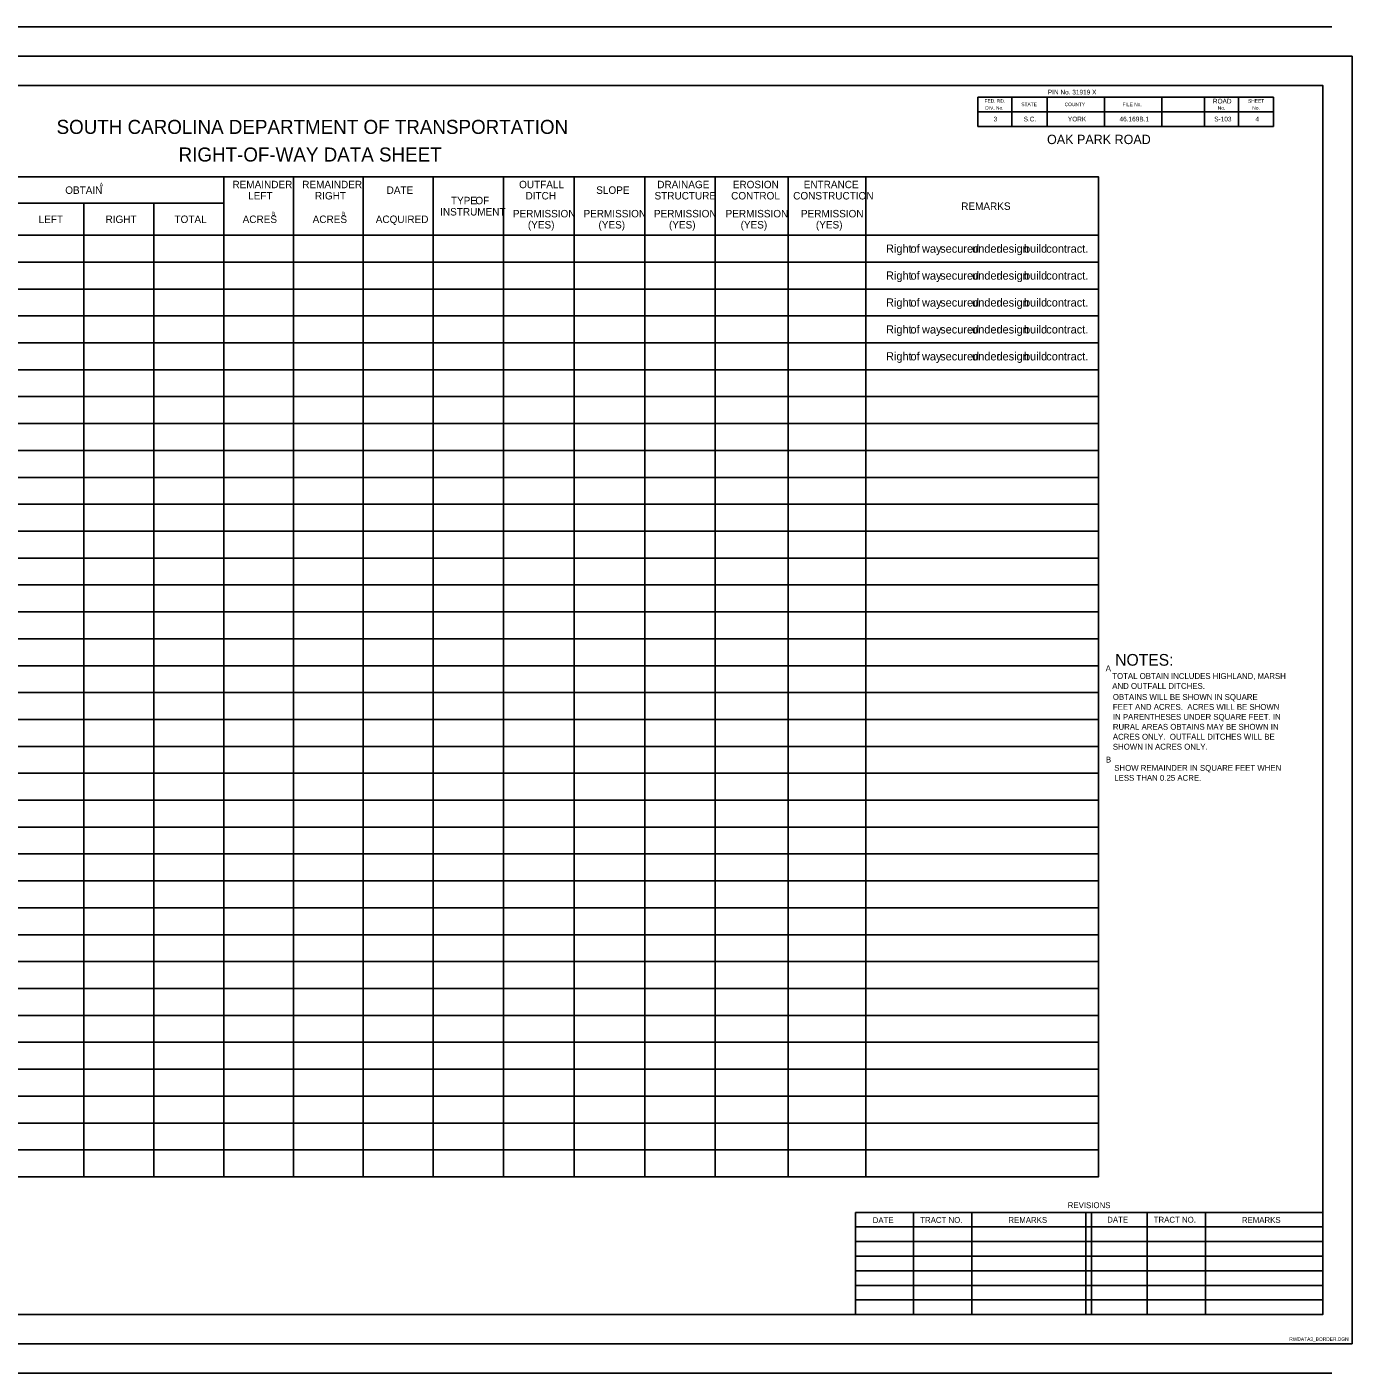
# Model space of a CAD drawing. Extents: x 9981 to 11777, y 9975 to 11125.
# Drawn here: x 10646 to 11777, y 9975 to 11125 of the extents above; entities that cross this region are included whole.
import ezdxf

# ---------------------------------------------------------------- set-up
doc = ezdxf.new("R2010")
doc.units = 0
for name, color, linetype in [('RD_SHT_Bndy', 7, 'Continuous'), ('RD_SHT_IplotShp', 7, 'Continuous'), ('RD_SHT_MjGrid', 7, 'Continuous'), ('RD_SHT_TX', 7, 'Continuous'), ('RD_TX_RW', 7, 'Continuous')]:
    doc.layers.add(name, color=color, linetype=linetype)

msp = doc.modelspace()

# ---------------------------------------------------------------- linework, layer by layer
at = {"layer": 'RD_SHT_Bndy'}
for p, q in [((10000, 11125), (11760, 11125)), ((10000, 11100), (11760, 11100)), ((11457.9, 11065), (11710.4, 11065)), ((11457.9, 11065), (11457.9, 11052.5)), ((11486.9, 11065), (11486.9, 11052.5)), ((11516.9, 11065), (11516.9, 11052.5)), ((11565.9, 11065), (11565.9, 11052.5)), ((11614.9, 11065), (11614.9, 11052.5)), ((11651.4, 11065), (11651.4, 11052.5)), ((11680.4, 11065), (11680.4, 11052.5)), ((11710.4, 11065), (11710.4, 11052.5)), ((11457.9, 11052.5), (11710.4, 11052.5)), ((11457.9, 11052.5), (11457.9, 11040)), ((11486.9, 11052.5), (11486.9, 11049.4)), ((11516.9, 11052.5), (11516.9, 11040)), ((11565.9, 11052.5), (11565.9, 11040)), ((11614.9, 11052.5), (11614.9, 11040)), ((11651.4, 11052.5), (11651.4, 11040)), ((11680.4, 11052.5), (11680.4, 11040)), ((11710.4, 11052.5), (11710.4, 11040)), ((11457.9, 11040), (11710.4, 11040)), ((11486.9, 11049.4), (11486.9, 11040)), ((11353.4, 10112.2), (11752.4, 10112.2)), ((11353.4, 10112.2), (11353.4, 10025)), ((11402.9, 10112.2), (11402.9, 10025)), ((11452.7, 10112.2), (11452.7, 10025)), ((11549.9, 10112.2), (11549.9, 10025)), ((11554.9, 10112.2), (11554.9, 10025)), ((11602.3, 10112.2), (11602.3, 10025)), ((11652.1, 10112.2), (11652.1, 10025)), ((11353.4, 10099.8), (11752.4, 10099.8)), ((11353.4, 10087.3), (11752.4, 10087.3)), ((11353.4, 10074.9), (11752.4, 10074.9)), ((11353.4, 10062.4), (11752.4, 10062.4)), ((11353.4, 10049.9), (11752.4, 10049.9)), ((11353.4, 10037.5), (11752.4, 10037.5)), ((10000, 10000), (11760, 10000)), ((10000, 9975), (11760, 9975))]:
    msp.add_line(p, q, dxfattribs=at)
for points in [[(10077.4, 11075), (11752.4, 11075), (11752.4, 10025), (10077.4, 10025)], [(10218, 10142.7), (11560.9, 10142.7), (11560.9, 10996.8), (10218, 10996.8)]]:
    msp.add_lwpolyline(points, close=True, dxfattribs=at)
at = {"layer": 'RD_SHT_IplotShp'}
msp.add_lwpolyline([(9981.4, 11100), (11777.4, 11100), (11777.4, 10000), (9981.4, 10000)], close=True, dxfattribs=at)
at = {"layer": 'RD_SHT_MjGrid'}
for p, q in [((10218, 10996.8), (11560.9, 10996.8)), ((10813.7, 10142.7), (10813.7, 10996.8)), ((10873.3, 10142.7), (10873.3, 10996.8)), ((10932.9, 10142.7), (10932.9, 10996.8)), ((10992.6, 10142.7), (10992.6, 10996.8)), ((11052.8, 10142.7), (11052.8, 10996.8)), ((11113.1, 10142.7), (11113.1, 10996.8)), ((11173.3, 10142.7), (11173.3, 10996.8)), ((11233.6, 10142.7), (11233.6, 10996.8)), ((11295.7, 10142.7), (11295.7, 10996.8)), ((11362.1, 10142.7), (11362.1, 10996.8)), ((11560.9, 10142.7), (11560.9, 10996.8)), ((10575.2, 10974.4), (10813.7, 10974.4)), ((10694.4, 10142.7), (10694.4, 10974.4)), ((10754, 10142.7), (10754, 10974.4)), ((10218, 10947.1), (11560.9, 10947.1)), ((10992.6, 10947.1), (11362.1, 10947.1)), ((11362.1, 10947.1), (11560.9, 10947.1)), ((10218, 10924.1), (11560.9, 10924.1)), ((10218, 10901.1), (11560.9, 10901.1)), ((10218, 10878.1), (11560.9, 10878.1)), ((10218, 10855.1), (11560.9, 10855.1)), ((10218, 10832.1), (11560.9, 10832.1)), ((10218, 10809.2), (11560.9, 10809.2)), ((10218, 10786.2), (11560.9, 10786.2)), ((10218, 10763.2), (11560.9, 10763.2)), ((10218, 10740.2), (11560.9, 10740.2)), ((10218, 10717.2), (11560.9, 10717.2)), ((10218, 10694.3), (11560.9, 10694.3)), ((10218, 10671.3), (11560.9, 10671.3)), ((10218, 10648.3), (11560.9, 10648.3)), ((10218, 10625.3), (11560.9, 10625.3)), ((10218, 10602.3), (11560.9, 10602.3)), ((10218, 10579.3), (11560.9, 10579.3)), ((10218, 10556.4), (11560.9, 10556.4)), ((10218, 10533.4), (11560.9, 10533.4)), ((10218, 10510.4), (11560.9, 10510.4)), ((10218, 10487.4), (11560.9, 10487.4)), ((10218, 10464.4), (11560.9, 10464.4)), ((10218, 10441.4), (11560.9, 10441.4)), ((10218, 10418.5), (11560.9, 10418.5)), ((10218, 10395.5), (11560.9, 10395.5)), ((10218, 10372.5), (11560.9, 10372.5)), ((10218, 10349.5), (11560.9, 10349.5)), ((10218, 10326.5), (11560.9, 10326.5)), ((10218, 10303.6), (11560.9, 10303.6)), ((10218, 10280.6), (11560.9, 10280.6)), ((10218, 10257.6), (11560.9, 10257.6)), ((10218, 10234.6), (11560.9, 10234.6)), ((10218, 10211.6), (11560.9, 10211.6)), ((10218, 10188.6), (11560.9, 10188.6)), ((10218, 10165.7), (11560.9, 10165.7)), ((10218, 10142.7), (11560.9, 10142.7))]:
    msp.add_line(p, q, dxfattribs=at)

# ---------------------------------------------------------------- texts
at = {"layer": 'RD_SHT_TX'}
for s, height, p in [('FED. RD.', 3, (11463.5, 11060.3)), ('PIN No. 31919 X   ', 4, (11517.6, 11067.3)), ('      ROAD      ', 4, (11649.3, 11059.6)), ('SHEET', 3, (11688.5, 11060.3)), ('DIV. No.', 3, (11464.1, 11054.3)), ('STATE', 3, (11494.9, 11057.3)), ('COUNTY', 3, (11531.9, 11057.3)), ('FILE No.', 3, (11581.4, 11057.3)), ('No.', 3, (11662.7, 11054.3)), ('No.', 3, (11692.2, 11054.3)), ('SOUTH CAROLINA DEPARTMENT OF TRANSPORTATION', 12, (10671, 11033.6)), ('3', 4, (11471.2, 11044.3)), ('S.C.', 4, (11496.9, 11044.3)), ('      YORK      ', 4, (11525.5, 11044.3)), ('   46.169B.1    ', 4, (11574.2, 11044.3)), ('     S-103      ', 4, (11652, 11044.3)), ('       4        ', 4, (11684.1, 11044.3)), ('OAK PARK ROAD                  ', 8, (11516.9, 11024.9)), ('RIGHT-OF-WAY DATA SHEET', 12, (10775.2, 11010)), ('NOTES:', 10, (11575.1, 10579.3)), ('A', 5, (11567, 10574.6)), ('TOTAL OBTAIN INCLUDES HIGHLAND, MARSH', 5, (11572.6, 10568)), ('AND OUTFALL DITCHES. ', 5, (11572.6, 10559.5)), ('OBTAINS WILL BE SHOWN IN SQUARE', 5, (11573.1, 10550.1)), ('FEET AND ACRES.  ACRES WILL BE SHOWN ', 5, (11573.1, 10541.6)), ('IN PARENTHESES UNDER SQUARE FEET. IN ', 5, (11573.1, 10533.1)), ('RURAL AREAS OBTAINS MAY BE SHOWN IN', 5, (11573.1, 10524.6)), ('ACRES ONLY.  OUTFALL DITCHES WILL BE', 5, (11573.1, 10516.1)), ('SHOWN IN ACRES ONLY.', 5, (11573.1, 10507.6)), ('B', 5, (11567.2, 10496.6)), ('SHOW REMAINDER IN SQUARE FEET WHEN ', 5, (11574.3, 10489.5)), ('LESS THAN 0.25 ACRE.', 5, (11574.3, 10481)), ('REVISIONS', 5, (11534.6, 10115.9)), ('DATE', 5, (11568.3, 10103.5)), ('TRACT NO.', 5, (11608, 10103.5)), ('DATE', 5, (11368, 10103.1)), ('TRACT NO.', 5, (11408.6, 10103.3)), ('REMARKS', 5, (11483.9, 10103.3)), ('REMARKS', 5, (11683.3, 10103.3)), ('RWDATA3_BORDER.DGN', 3, (11723.8, 10002.5))]:
    msp.add_text(s, height=height, dxfattribs=at).set_placement(p)
at = {"layer": 'RD_TX_RW'}
for s, height, p in [('OBTAIN', 6.37, (10678.4, 10982.4)), ('A', 3.19, (10707.8, 10988.8)), ('REMAINDER', 6.37, (10821.2, 10987.2)), ('LEFT', 6.37, (10834.6, 10977.6)), ('REMAINDER', 6.37, (10880.8, 10987.2)), ('RIGHT', 6.37, (10891.7, 10977.6)), ('DATE', 6.37, (10952.9, 10982.4)), ('OUTFALL', 6.37, (11066, 10987.2)), ('DITCH', 6.37, (11071.5, 10977.6)), ('SLOPE', 6.37, (11131.9, 10982.4)), ('STRUCTURE', 6.37, (11181.7, 10977.6)), ('DRAINAGE', 6.37, (11184, 10987.2)), ('CONTROL', 6.37, (11247.1, 10977.6)), ('EROSION', 6.37, (11248.5, 10987.2)), ('CONSTRUCTION', 6.371, (11300.1, 10977.6)), ('ENTRANCE', 6.37, (11309.1, 10987.2)), ('TYPE', 6.37, (11007.8, 10973.5)), (' OF', 6.37, (11026.3, 10973.5)), ('REMARKS', 6.37, (11443.6, 10968.7)), ('LEFT', 6.37, (10655.7, 10957.5)), ('RIGHT', 6.37, (10712.8, 10957.5)), ('TOTAL', 6.37, (10771.7, 10957.5)), ('ACRES', 6.37, (10829.9, 10957.5)), ('B', 3.19, (10854.8, 10963.9)), ('ACRES', 6.37, (10889.7, 10957.5)), (' B', 3.19, (10913.4, 10963.9)), ('ACQUIRED', 6.37, (10943.6, 10957.5)), ('INSTRUMENT', 6.37, (10998.6, 10963.9)), ('PERMISSION', 6.37, (11060.7, 10962.3)), ('PERMISSION', 6.37, (11121, 10962.3)), ('PERMISSION', 6.37, (11181.2, 10962.3)), ('PERMISSION', 6.37, (11242.4, 10962.3)), ('PERMISSION', 6.37, (11306.7, 10962.3)), ('(YES)', 6.37, (11073.5, 10952.8)), ('(YES)', 6.37, (11133.8, 10952.8)), ('(YES)', 6.37, (11194, 10952.8)), ('(YES)', 6.37, (11255.2, 10952.8)), ('(YES)', 6.37, (11319.5, 10952.8)), ('Right', 7.01, (11379.4, 10932.1)), (' of', 7.01, (11397.7, 10932.1)), (' way', 7.01, (11407.5, 10932.1)), (' secured', 7.01, (11423, 10932.1)), (' under', 7.01, (11450.3, 10932.1)), (' design', 7.01, (11471.1, 10932.1)), (' build', 7.01, (11494.6, 10932.1)), (' contract.', 7.01, (11513.6, 10932.1)), ('Right', 7.01, (11379.4, 10909.1)), (' of', 7.01, (11397.7, 10909.1)), (' way', 7.01, (11407.5, 10909.1)), (' secured', 7.01, (11423, 10909.1)), (' under', 7.01, (11450.3, 10909.1)), (' design', 7.01, (11471.1, 10909.1)), (' build', 7.01, (11494.6, 10909.1)), (' contract.', 7.01, (11513.6, 10909.1)), ('Right', 7.01, (11379.4, 10886.1)), (' of', 7.01, (11397.7, 10886.1)), (' way', 7.01, (11407.5, 10886.1)), (' secured', 7.01, (11423, 10886.1)), (' under', 7.01, (11450.3, 10886.1)), (' design', 7.01, (11471.1, 10886.1)), (' build', 7.01, (11494.6, 10886.1)), (' contract.', 7.01, (11513.6, 10886.1)), ('Right', 7.01, (11379.4, 10863.1)), (' of', 7.01, (11397.7, 10863.1)), (' way', 7.01, (11407.5, 10863.1)), (' secured', 7.01, (11423, 10863.1)), (' under', 7.01, (11450.3, 10863.1)), (' design', 7.01, (11471.1, 10863.1)), (' build', 7.01, (11494.6, 10863.1)), (' contract.', 7.01, (11513.6, 10863.1)), ('Right', 7.01, (11379.4, 10840.1)), (' of', 7.01, (11397.7, 10840.1)), (' way', 7.01, (11407.5, 10840.1)), (' secured', 7.01, (11423, 10840.1)), (' under', 7.01, (11450.3, 10840.1)), (' design', 7.01, (11471.1, 10840.1)), (' build', 7.01, (11494.6, 10840.1)), (' contract.', 7.01, (11513.6, 10840.1))]:
    msp.add_text(s, height=height, dxfattribs=at).set_placement(p)

doc.saveas('drawing.dxf')
